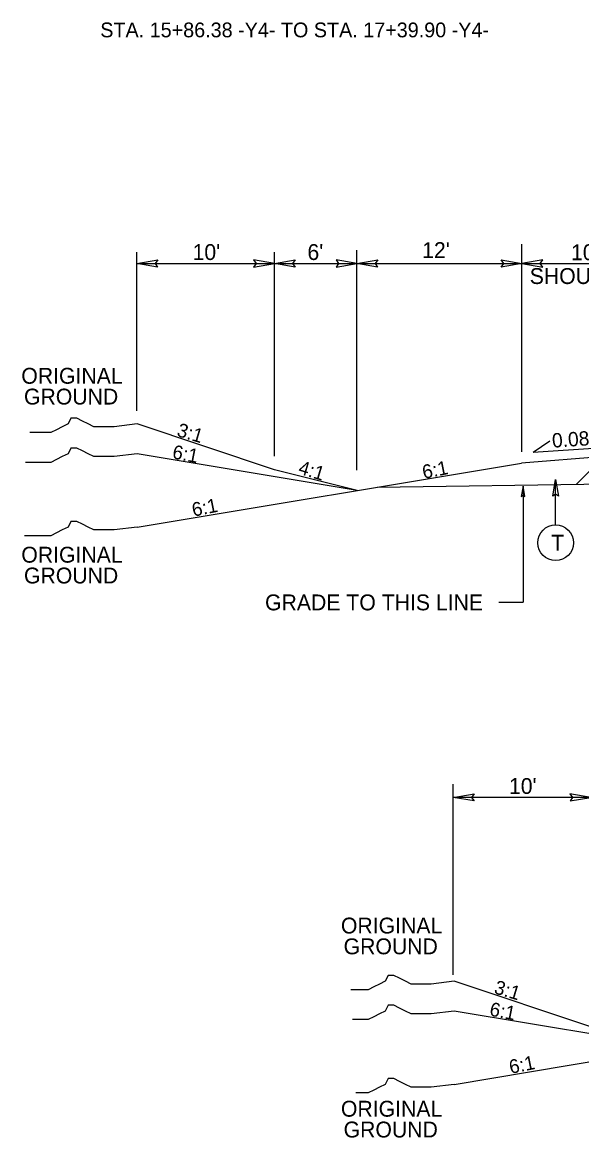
# Model space of a CAD drawing. Extents: x 2176156 to 2177167, y 76401 to 76644.
# Drawn here: x 2176223.4 to 2176264, y 76469.1 to 76550.2 of the extents above; entities that cross this region are included whole.
import ezdxf

# ---------------------------------------------------------------- set-up
doc = ezdxf.new("R2010")
doc.units = 0
for name, color, linetype in [('Exist Building', 7, 'Continuous'), ('Exist Roads Curbs', 7, 'Continuous'), ('Exist Roads EOP Other', 7, 'Continuous'), ('Exist Roads Soil', 7, 'Continuous'), ('Exist Structure Minor Culvert Topo', 7, 'Continuous'), ('Exist Utilities Other Pole CELL', 7, 'Continuous'), ('Exist Vegetation Woods Line', 7, 'Continuous'), ('Old_Level_1', 7, 'Continuous'), ('Old_Level_3', 7, 'Continuous'), ('Prop North Arrow NAD83 for Plan Sheets CELL', 7, 'Continuous')]:
    doc.layers.add(name, color=color, linetype=linetype)

msp = doc.modelspace()

# ---------------------------------------------------------------- linework, layer by layer
at = {"layer": 'Exist Building'}
msp.add_line((2176249.154, 76516.4), (2176278.832, 76516.842), dxfattribs=at)
at = {"layer": 'Exist Roads Curbs'}
for points in [[(2176231.702, 76520.991), (2176230.031, 76520.783), (2176229.614, 76520.783), (2176228.986, 76520.783), (2176228.569, 76520.783), (2176228.151, 76520.991), (2176227.733, 76521.201), (2176227.316, 76521.411), (2176226.898, 76521.411), (2176226.688, 76520.991), (2176226.271, 76520.783), (2176225.853, 76520.574), (2176225.435, 76520.366), (2176225.018, 76520.366), (2176224.6, 76520.366), (2176224.182, 76520.366), (2176223.911, 76520.366)], [(2176231.702, 76518.825), (2176230.031, 76518.617), (2176229.613, 76518.617), (2176228.986, 76518.617), (2176228.568, 76518.617), (2176228.151, 76518.825), (2176227.733, 76519.034), (2176227.315, 76519.244), (2176226.898, 76519.244), (2176226.688, 76518.825), (2176226.27, 76518.617), (2176225.853, 76518.407), (2176225.435, 76518.199), (2176225.017, 76518.199), (2176224.6, 76518.199), (2176224.182, 76518.199), (2176223.764, 76518.199), (2176223.601, 76518.199)], [(2176231.702, 76513.491), (2176230.031, 76513.283), (2176229.614, 76513.283), (2176228.986, 76513.283), (2176228.569, 76513.283), (2176228.151, 76513.491), (2176227.733, 76513.701), (2176227.316, 76513.911), (2176226.898, 76513.911), (2176226.688, 76513.491), (2176226.271, 76513.283), (2176225.853, 76513.074), (2176225.435, 76512.866), (2176225.018, 76512.866), (2176224.6, 76512.866), (2176224.182, 76512.866), (2176223.765, 76512.866), (2176223.524, 76512.866)], [(2176254.767, 76480.477), (2176253.096, 76480.269), (2176252.679, 76480.269), (2176252.051, 76480.269), (2176251.634, 76480.269), (2176251.216, 76480.477), (2176250.798, 76480.687), (2176250.381, 76480.896), (2176249.963, 76480.896), (2176249.753, 76480.477), (2176249.336, 76480.269), (2176248.918, 76480.059), (2176248.5, 76479.852), (2176248.083, 76479.852), (2176247.665, 76479.852), (2176247.249, 76479.852)], [(2176254.767, 76478.31), (2176253.096, 76478.102), (2176252.678, 76478.102), (2176252.051, 76478.102), (2176251.633, 76478.102), (2176251.216, 76478.31), (2176250.798, 76478.52), (2176250.38, 76478.73), (2176249.963, 76478.73), (2176249.753, 76478.31), (2176249.335, 76478.102), (2176248.918, 76477.893), (2176248.5, 76477.685), (2176248.082, 76477.685), (2176247.665, 76477.685), (2176247.382, 76477.685)], [(2176254.767, 76472.977), (2176253.096, 76472.769), (2176252.679, 76472.769), (2176252.051, 76472.769), (2176251.634, 76472.769), (2176251.216, 76472.977), (2176250.798, 76473.187), (2176250.381, 76473.396), (2176249.963, 76473.396), (2176249.753, 76472.977), (2176249.336, 76472.769), (2176248.918, 76472.559), (2176248.5, 76472.352), (2176248.083, 76472.352), (2176247.665, 76472.352), (2176247.603, 76472.352)]]:
    msp.add_lwpolyline(points, dxfattribs=at)
at = {"layer": 'Exist Roads EOP Other'}
for p, q in [((2176241.702, 76517.658), (2176231.702, 76520.991)), ((2176265.689, 76518.633), (2176259.654, 76518.15)), ((2176247.702, 76516.158), (2176241.702, 76517.658)), ((2176264.767, 76477.144), (2176254.767, 76480.477))]:
    msp.add_line(p, q, dxfattribs=at)
at = {"layer": 'Exist Roads Soil'}
for p, q in [((2176247.702, 76516.158), (2176231.702, 76518.825)), ((2176265.689, 76518.633), (2176263.661, 76516.616)), ((2176231.702, 76513.491), (2176259.654, 76518.15)), ((2176270.767, 76475.644), (2176254.767, 76478.31)), ((2176254.767, 76472.977), (2176282.719, 76477.636))]:
    msp.add_line(p, q, dxfattribs=at)
at = {"layer": 'Exist Utilities Other Pole CELL'}
for q in [(2176261.727, 76519.754), (2176265.249, 76519.249)]:
    msp.add_line((2176260.503, 76518.935), q, dxfattribs=at)
at = {"layer": 'Old_Level_1'}
for points in [[(2176233.199, 76532.402), (2176231.689, 76532.662), (2176233.207, 76532.93), (2176233.014, 76532.662)], [(2176240.179, 76532.402), (2176241.689, 76532.662), (2176240.171, 76532.93), (2176240.364, 76532.662)], [(2176243.199, 76532.402), (2176241.689, 76532.662), (2176243.207, 76532.93), (2176243.014, 76532.662)], [(2176246.179, 76532.402), (2176247.689, 76532.662), (2176246.171, 76532.93), (2176246.364, 76532.662)], [(2176249.199, 76532.402), (2176247.689, 76532.662), (2176249.207, 76532.93), (2176249.014, 76532.662)], [(2176258.179, 76532.922), (2176259.689, 76532.662), (2176258.171, 76532.393), (2176258.364, 76532.662)], [(2176261.199, 76532.922), (2176259.689, 76532.662), (2176261.207, 76532.393), (2176261.014, 76532.662)], [(2176259.899, 76515.717), (2176259.769, 76516.472), (2176259.635, 76515.713), (2176259.769, 76515.809)], [(2176256.205, 76493.58), (2176254.695, 76493.84), (2176256.213, 76494.108), (2176256.02, 76493.84)], [(2176263.185, 76493.58), (2176264.695, 76493.84), (2176263.177, 76494.108), (2176263.37, 76493.84)]]:
    msp.add_lwpolyline(points, close=True, dxfattribs=at)
at = {"layer": 'Old_Level_3'}
for p, q in [((2176259.689, 76518.97), (2176259.689, 76534.057)), ((2176231.689, 76521.954), (2176231.689, 76533.494)), ((2176241.689, 76518.652), (2176241.689, 76533.494)), ((2176247.689, 76517.634), (2176247.689, 76533.627)), ((2176231.689, 76532.662), (2176295.689, 76532.662)), ((2176259.769, 76516.472), (2176259.769, 76508.046)), ((2176258.002, 76508.046), (2176259.769, 76508.046)), ((2176254.695, 76480.946), (2176254.695, 76494.793)), ((2176264.695, 76493.84), (2176254.695, 76493.84))]:
    msp.add_line(p, q, dxfattribs=at)
at = {"layer": 'Prop North Arrow NAD83 for Plan Sheets CELL'}
msp.add_line((2176262.14, 76513.652), (2176262.14, 76516.948), dxfattribs=at)
msp.add_lwpolyline([(2176261.933, 76515.748), (2176262.14, 76516.948), (2176262.353, 76515.742), (2176262.14, 76515.895)], close=True, dxfattribs=at)
msp.add_circle((2176262.14, 76512.356), 1.296, dxfattribs=at)

# ---------------------------------------------------------------- texts
at = {"layer": 'Exist Roads Curbs'}
for s, rotation, p in [('3:1', 343.53506, (2176234.537, 76520.124)), ('6:1', 349.18318, (2176234.218, 76518.496)), ('4:1', 343.53506, (2176243.369, 76517.391)), ('6:1', 11.48655, (2176252.554, 76516.988)), ('6:1', 11.48655, (2176235.804, 76514.247)), ('3:1', 343.53506, (2176257.602, 76479.61)), ('6:1', 349.18318, (2176257.283, 76477.982)), ('6:1', 11.48655, (2176258.869, 76473.733))]:
    msp.add_text(s, height=1.0064, rotation=rotation, dxfattribs=at).set_placement(p)
at = {"layer": 'Exist Structure Minor Culvert Topo'}
for s, height, p in [("10'", 1.1533, (2176235.741, 76532.914)), ("6'", 1.1533, (2176244.095, 76532.914)), ("12' ", 1.1533, (2176252.434, 76533.057)), ("10' ", 1.1533, (2176263.259, 76532.899)), ('SHOULDER', 1.1533, (2176260.257, 76531.169)), ('ORIGINAL', 1.1533, (2176223.288, 76523.918)), ('GROUND', 1.1533, (2176223.482, 76522.406)), ('ORIGINAL', 1.1533, (2176223.288, 76510.909)), ('GROUND', 1.1533, (2176223.482, 76509.397)), ('GRADE TO THIS LINE', 1.15334, (2176241.01, 76507.442)), ("10'", 1.1533, (2176258.747, 76494.092)), ('ORIGINAL', 1.1533, (2176246.529, 76483.946)), ('GROUND', 1.1533, (2176246.723, 76482.434)), ('ORIGINAL', 1.1533, (2176246.529, 76470.628)), ('GROUND', 1.1533, (2176246.723, 76469.116))]:
    msp.add_text(s, height=height, dxfattribs=at).set_placement(p)
at = {"layer": 'Exist Utilities Other Pole CELL'}
msp.add_text('0.08', height=1.0429, rotation=3.78012, dxfattribs=at).set_placement((2176261.913, 76519.265))
at = {"layer": 'Exist Vegetation Woods Line'}
msp.add_text('STA. 15+86.38 -Y4- TO STA. 17+39.90 -Y4-', height=1.0742, dxfattribs=at).set_placement((2176229.03, 76549.105))
at = {"layer": 'Prop North Arrow NAD83 for Plan Sheets CELL'}
msp.add_text('T', height=1.16, rotation=0.00026, dxfattribs=at).set_placement((2176261.813, 76511.776))

doc.saveas('drawing.dxf')
